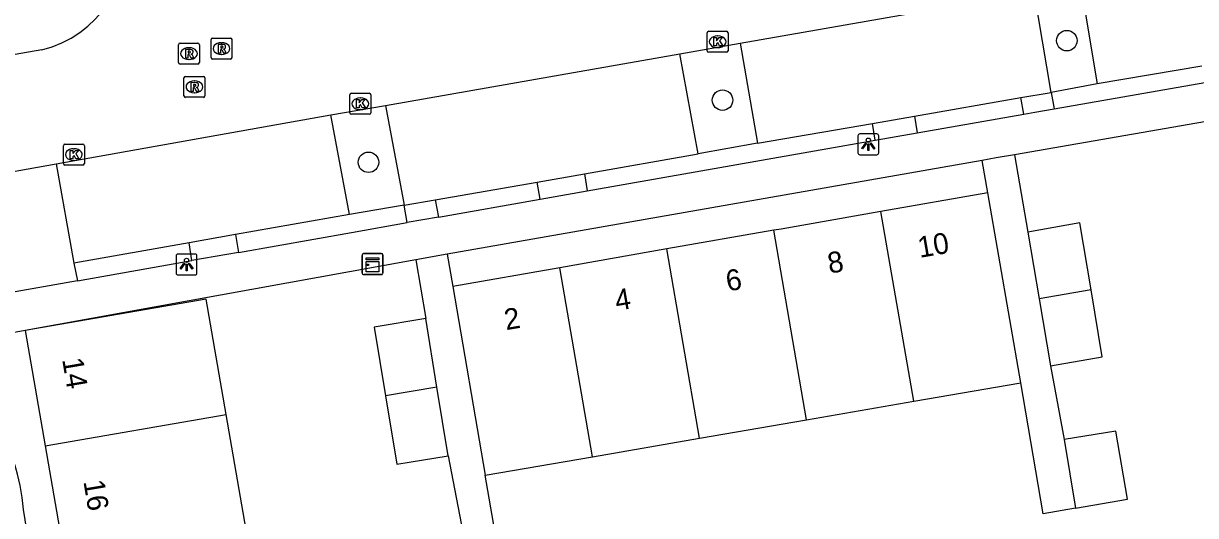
# Model space of a CAD drawing. Extents: x 160158 to 160921, y 381517 to 382041.
# Drawn here: x 160426.6 to 160482.6, y 381562.6 to 381586.1 of the extents above; entities that cross this region are included whole.
import ezdxf

# ---------------------------------------------------------------- set-up
doc = ezdxf.new("R2010")
doc.units = 0
for name, color, linetype in [('IMGEO_Boom', 7, 'Continuous'), ('IMGEO_Haag', 7, 'Continuous'), ('IMGEO_Kast', 7, 'Continuous'), ('IMGEO_Kolk', 7, 'Continuous'), ('IMGEO_Lichtpunt', 7, 'Continuous'), ('IMGEO_Pand', 7, 'Continuous'), ('IMGEO_Pand_nummerreeks', 7, 'Continuous'), ('IMGEO_Parkeervlak_open', 7, 'Continuous'), ('IMGEO_Rijbaan_lokaal_open', 7, 'Continuous'), ('IMGEO_Rioolput', 7, 'Continuous'), ('IMGEO_Voetpad_open', 7, 'Continuous')]:
    doc.layers.add(name, color=color, linetype=linetype)

msp = doc.modelspace()

# ---------------------------------------------------------------- linework, layer by layer
at = {"layer": 'IMGEO_Boom'}
for centre in [(160476.481, 381585.284), (160460.03, 381582.444), (160443.111, 381579.477)]:
    msp.add_circle(centre, 0.489, dxfattribs=at)
at = {"layer": 'IMGEO_Haag'}
for points in [[(160477.934, 381583.215), (160475.736, 381582.816)], [(160461.706, 381580.383), (160458.87, 381579.878)], [(160444.822, 381577.426), (160442.204, 381576.98)], [(160429.039, 381574.668), (160429.203, 381573.814)]]:
    msp.add_lwpolyline(points, dxfattribs=at)
at = {"layer": 'IMGEO_Kast'}
for p, q in [((160442.805, 381574.193), (160442.805, 381575.034)), ((160442.805, 381575.034), (160442.805, 381574.193)), ((160442.88, 381575.118), (160443.721, 381575.118)), ((160443.721, 381575.118), (160442.88, 381575.118)), ((160443.805, 381575.043), (160443.805, 381574.202)), ((160443.805, 381574.202), (160443.805, 381575.043)), ((160443.73, 381574.118), (160442.889, 381574.118)), ((160442.889, 381574.118), (160443.73, 381574.118))]:
    msp.add_line(p, q, dxfattribs=at)
for points in [[(160443, 381574.908), (160443.6, 381574.908), (160443.6, 381574.823), (160443, 381574.823), (160443, 381574.908)], [(160443, 381574.733), (160443.6, 381574.733), (160443.6, 381574.244), (160443, 381574.244), (160443, 381574.733)]]:
    msp.add_lwpolyline(points, dxfattribs=at)
msp.add_circle((160443.084, 381574.582), 0.0377, dxfattribs=at)
for centre, start, end in [((160442.883, 381575.04), 92.4484, 184.2845), ((160442.883, 381575.04), 92.4484, 184.2845), ((160443.727, 381575.04), 2.4484, 94.2845), ((160443.727, 381575.04), 2.4484, 94.2845), ((160442.883, 381574.196), 182.4484, 274.2845), ((160442.883, 381574.196), 182.4484, 274.2845), ((160443.727, 381574.196), 272.4484, 4.2845), ((160443.727, 381574.196), 272.4484, 4.2845)]:
    msp.add_arc(centre, 0.0779, start, end, dxfattribs=at)
at = {"layer": 'IMGEO_Kolk'}
for p, q in [((160459.296, 381584.805), (160459.296, 381585.657)), ((160459.371, 381585.731), (160460.223, 381585.731)), ((160460.297, 381585.657), (160460.297, 381584.805)), ((160459.784, 381585.511), (160459.809, 381585.511)), ((160460.223, 381584.731), (160459.371, 381584.731)), ((160459.807, 381584.951), (160459.782, 381584.951)), ((160442.298, 381582.77), (160443.15, 381582.77)), ((160442.223, 381581.844), (160442.223, 381582.696)), ((160442.711, 381582.55), (160442.736, 381582.55)), ((160443.224, 381582.696), (160443.224, 381581.844)), ((160443.15, 381581.77), (160442.298, 381581.77)), ((160442.734, 381581.99), (160442.709, 381581.99)), ((160428.536, 381579.418), (160428.536, 381580.27)), ((160428.611, 381580.344), (160429.463, 381580.344)), ((160429.024, 381580.124), (160429.049, 381580.124)), ((160429.537, 381580.27), (160429.537, 381579.418)), ((160429.047, 381579.564), (160429.022, 381579.564)), ((160429.463, 381579.344), (160428.611, 381579.344))]:
    msp.add_line(p, q, dxfattribs=at)
for points in [[(160459.296, 381584.805), (160459.296, 381585.657)], [(160459.371, 381585.731), (160460.223, 381585.731)], [(160460.297, 381585.657), (160460.297, 381584.805)], [(160459.617, 381585.431), (160459.74, 381585.431), (160459.74, 381585.28), (160459.87, 381585.431), (160460.034, 381585.431), (160459.888, 381585.28), (160460.041, 381585.031), (160459.889, 381585.031), (160459.804, 381585.195), (160459.74, 381585.128), (160459.74, 381585.031), (160459.617, 381585.031), (160459.617, 381585.431)], [(160460.223, 381584.731), (160459.371, 381584.731)], [(160442.298, 381582.77), (160443.15, 381582.77)], [(160442.223, 381581.844), (160442.223, 381582.696)], [(160442.544, 381582.47), (160442.667, 381582.47), (160442.667, 381582.319), (160442.797, 381582.47), (160442.961, 381582.47), (160442.815, 381582.319), (160442.968, 381582.07), (160442.816, 381582.07), (160442.731, 381582.234), (160442.667, 381582.167), (160442.667, 381582.07), (160442.544, 381582.07), (160442.544, 381582.47)], [(160443.224, 381582.696), (160443.224, 381581.844)], [(160443.15, 381581.77), (160442.298, 381581.77)], [(160428.536, 381579.418), (160428.536, 381580.27)], [(160428.611, 381580.344), (160429.463, 381580.344)], [(160428.857, 381580.044), (160428.98, 381580.044), (160428.98, 381579.893), (160429.11, 381580.044), (160429.274, 381580.044), (160429.128, 381579.893), (160429.281, 381579.644), (160429.129, 381579.644), (160429.044, 381579.808), (160428.98, 381579.741), (160428.98, 381579.644), (160428.857, 381579.644), (160428.857, 381580.044)], [(160429.537, 381580.27), (160429.537, 381579.418)], [(160429.463, 381579.344), (160428.611, 381579.344)]]:
    msp.add_lwpolyline(points, dxfattribs=at)
for centre, start, end in [((160459.373, 381585.655), 91.552, 178.448), ((160459.373, 381585.655), 91.552, 178.448), ((160460.221, 381585.655), 1.552, 88.448), ((160460.221, 381585.655), 1.552, 88.448), ((160459.373, 381584.807), 181.552, 268.448), ((160459.373, 381584.807), 181.552, 268.448), ((160460.221, 381584.807), 271.552, 358.448), ((160460.221, 381584.807), 271.552, 358.448), ((160442.3, 381582.694), 91.552, 178.448), ((160442.3, 381582.694), 91.552, 178.448), ((160443.148, 381582.694), 1.552, 88.448), ((160443.148, 381582.694), 1.552, 88.448), ((160442.3, 381581.846), 181.552, 268.448), ((160442.3, 381581.846), 181.552, 268.448), ((160443.148, 381581.846), 271.552, 358.448), ((160443.148, 381581.846), 271.552, 358.448), ((160428.613, 381580.268), 91.552, 178.448), ((160428.613, 381580.268), 91.552, 178.448), ((160429.461, 381580.268), 1.552, 88.448), ((160429.461, 381580.268), 1.552, 88.448), ((160428.613, 381579.42), 181.552, 268.448), ((160428.613, 381579.42), 181.552, 268.448), ((160429.461, 381579.42), 271.552, 358.448), ((160429.461, 381579.42), 271.552, 358.448)]:
    msp.add_arc(centre, 0.0765, start, end, dxfattribs=at)
for centre, major_axis, ratio, start_param, end_param in [((160459.783, 381585.231), (-0.387, 0.002), 0.722429, 4.712389, 7.853982), ((160459.808, 381585.231), (-0.39, 0.002), 0.717154, 1.570796, 4.712389), ((160442.71, 381582.27), (-0.387, 0.002), 0.722429, 4.712389, 7.853982), ((160442.735, 381582.27), (-0.39, 0.002), 0.717154, 1.570796, 4.712389), ((160429.023, 381579.844), (-0.387, 0.002), 0.722429, 4.712389, 7.853982), ((160429.048, 381579.844), (-0.39, 0.002), 0.717154, 1.570796, 4.712389)]:
    msp.add_ellipse(centre, major_axis=major_axis, ratio=ratio, start_param=start_param, end_param=end_param, dxfattribs=at)
at = {"layer": 'IMGEO_Lichtpunt'}
for p, q in [((160466.497, 381580.738), (160466.497, 381579.931)), ((160466.497, 381580.738), (160466.497, 381579.931)), ((160467.399, 381580.833), (160466.591, 381580.833)), ((160467.399, 381580.833), (160466.591, 381580.833)), ((160467.493, 381579.931), (160467.493, 381580.738)), ((160467.493, 381579.931), (160467.493, 381580.738)), ((160466.591, 381579.837), (160467.399, 381579.837)), ((160466.591, 381579.837), (160467.399, 381579.837)), ((160433.922, 381575.001), (160433.922, 381574.194)), ((160433.922, 381575.001), (160433.922, 381574.194)), ((160434.824, 381575.096), (160434.016, 381575.096)), ((160434.824, 381575.096), (160434.016, 381575.096)), ((160434.918, 381574.194), (160434.918, 381575.001)), ((160434.918, 381574.194), (160434.918, 381575.001)), ((160434.016, 381574.1), (160434.824, 381574.1)), ((160434.016, 381574.1), (160434.824, 381574.1))]:
    msp.add_line(p, q, dxfattribs=at)
for points in [[(160466.871, 381580.402), (160466.91, 381580.374), (160466.722, 381580.112), (160466.684, 381580.139), (160466.871, 381580.402)], [(160466.973, 381580.354), (160467.02, 381580.354), (160467.02, 381580.032), (160466.973, 381580.032), (160466.973, 381580.354)], [(160467.083, 381580.374), (160467.121, 381580.401), (160467.308, 381580.139), (160467.269, 381580.111), (160467.083, 381580.374)], [(160434.296, 381574.665), (160434.335, 381574.637), (160434.147, 381574.375), (160434.109, 381574.402), (160434.296, 381574.665)], [(160434.398, 381574.617), (160434.445, 381574.617), (160434.445, 381574.295), (160434.398, 381574.295), (160434.398, 381574.617)], [(160434.508, 381574.637), (160434.546, 381574.664), (160434.733, 381574.402), (160434.694, 381574.374), (160434.508, 381574.637)]]:
    msp.add_lwpolyline(points, dxfattribs=at)
for centre in [(160466.996, 381580.536), (160434.421, 381574.799)]:
    msp.add_circle(centre, 0.0994, dxfattribs=at)
for centre, start, end in [((160466.591, 381580.738), 90, 180), ((160466.591, 381580.738), 90, 180), ((160467.399, 381580.738), 0, 90), ((160467.399, 381580.738), 0, 90), ((160466.591, 381579.931), 180, 270), ((160466.591, 381579.931), 180, 270), ((160467.399, 381579.931), 270, 0), ((160467.399, 381579.931), 270, 360), ((160434.016, 381575.001), 90, 180), ((160434.016, 381575.001), 90, 180), ((160434.824, 381575.001), 0, 90), ((160434.824, 381575.001), 0, 90), ((160434.016, 381574.194), 180, 270), ((160434.016, 381574.194), 180, 270), ((160434.824, 381574.194), 270, 0), ((160434.824, 381574.194), 270, 360)]:
    msp.add_arc(centre, 0.0946, start, end, dxfattribs=at)
at = {"layer": 'IMGEO_Pand'}
for points in [[(160472.714, 381578.016), (160467.601, 381577.123)], [(160474.281, 381568.948), (160472.714, 381578.016)], [(160467.601, 381577.123), (160462.828, 381576.289), (160462.488, 381576.23)], [(160469.164, 381568.066), (160467.601, 381577.123)], [(160477.637, 381573.391), (160477.097, 381576.593), (160474.621, 381576.147)], [(160462.488, 381576.23), (160457.375, 381575.337)], [(160464.047, 381567.185), (160462.488, 381576.23)], [(160474.621, 381576.147), (160475.162, 381572.954)], [(160457.375, 381575.337), (160452.262, 381574.444)], [(160458.929, 381566.303), (160457.375, 381575.337)], [(160452.262, 381574.444), (160447.149, 381573.551)], [(160453.812, 381565.422), (160452.262, 381574.444)], [(160447.149, 381573.551), (160448.695, 381564.54)], [(160477.637, 381573.391), (160475.162, 381572.954)], [(160475.702, 381569.761), (160478.177, 381570.188), (160477.637, 381573.391)], [(160436.314, 381567.442), (160435.356, 381572.949), (160426.71, 381571.443)], [(160475.162, 381572.954), (160475.702, 381569.761)], [(160445.847, 381572.014), (160443.389, 381571.602), (160443.928, 381568.33)], [(160446.387, 381568.739), (160445.847, 381572.014)], [(160426.71, 381571.443), (160427.667, 381565.936)], [(160469.164, 381568.066), (160474.281, 381568.948)], [(160446.387, 381568.739), (160443.928, 381568.33)], [(160443.928, 381568.33), (160444.468, 381565.058), (160446.927, 381565.464)], [(160446.927, 381565.464), (160446.387, 381568.739)], [(160464.047, 381567.185), (160469.164, 381568.066)], [(160427.667, 381565.936), (160436.314, 381567.442)], [(160437.271, 381561.934), (160436.314, 381567.442)], [(160458.929, 381566.303), (160464.047, 381567.185)], [(160476.902, 381562.957), (160479.376, 381563.387), (160478.83, 381566.646), (160476.347, 381566.239)], [(160453.812, 381565.422), (160458.929, 381566.303)], [(160476.347, 381566.239), (160476.902, 381562.957)], [(160427.667, 381565.936), (160428.625, 381560.43)], [(160448.695, 381564.54), (160453.812, 381565.422)]]:
    msp.add_lwpolyline(points, dxfattribs=at)
at = {"layer": 'IMGEO_Parkeervlak_open'}
for points in [[(160477.14, 381588.004), (160477.934, 381583.215)], [(160475.736, 381582.816), (160474.925, 381587.623)], [(160460.872, 381585.165), (160461.706, 381580.383)], [(160458.87, 381579.878), (160457.992, 381584.659)], [(160482.925, 381584.072), (160477.934, 381583.215)], [(160469.197, 381581.682), (160474.29, 381582.565)], [(160442.204, 381576.98), (160441.322, 381581.744)], [(160443.92, 381582.187), (160444.822, 381577.426)], [(160461.706, 381580.383), (160467.188, 381581.334)], [(160428.192, 381579.402), (160429.039, 381574.668)], [(160453.429, 381578.928), (160458.87, 381579.878)], [(160446.299, 381577.684), (160451.17, 381578.534)], [(160442.204, 381576.98), (160436.753, 381576.023)], [(160434.543, 381575.635), (160429.039, 381574.668)]]:
    msp.add_lwpolyline(points, dxfattribs=at)
at = {"layer": 'IMGEO_Rijbaan_lokaal_open'}
for points in [[(160460.872, 381585.165), (160474.925, 381587.623)], [(160457.992, 381584.659), (160460.872, 381585.165)], [(160427.508, 381584.838), (160422.1, 381583.909)], [(160443.92, 381582.187), (160457.992, 381584.659)], [(160428.192, 381579.402), (160441.322, 381581.744)], [(160441.322, 381581.744), (160443.92, 381582.187)], [(160424.425, 381578.731), (160428.192, 381579.402)]]:
    msp.add_lwpolyline(points, dxfattribs=at)
msp.add_arc((160426.158, 381590.124), 5.456, 284.3246, 7.1148, dxfattribs=at)
at = {"layer": 'IMGEO_Rioolput'}
for p, q in [((160434.036, 381584.239), (160434.036, 381585.091)), ((160434.111, 381585.165), (160434.963, 381585.165)), ((160435.037, 381585.091), (160435.037, 381584.239)), ((160435.591, 381584.481), (160435.591, 381585.333)), ((160435.666, 381585.407), (160436.518, 381585.407)), ((160436.079, 381585.187), (160436.104, 381585.187)), ((160436.592, 381585.333), (160436.592, 381584.481)), ((160434.524, 381584.945), (160434.549, 381584.945)), ((160436.102, 381584.627), (160436.077, 381584.627)), ((160434.963, 381584.165), (160434.111, 381584.165)), ((160434.547, 381584.385), (160434.522, 381584.385)), ((160436.518, 381584.407), (160435.666, 381584.407)), ((160434.296, 381582.652), (160434.296, 381583.504)), ((160434.371, 381583.578), (160435.223, 381583.578)), ((160434.784, 381583.358), (160434.809, 381583.358)), ((160435.297, 381583.504), (160435.297, 381582.652)), ((160434.807, 381582.798), (160434.782, 381582.798)), ((160435.223, 381582.578), (160434.371, 381582.578))]:
    msp.add_line(p, q, dxfattribs=at)
for points in [[(160434.036, 381584.239), (160434.036, 381585.091)], [(160434.111, 381585.165), (160434.963, 381585.165)], [(160435.037, 381585.091), (160435.037, 381584.239)], [(160435.591, 381584.481), (160435.591, 381585.333)], [(160435.666, 381585.407), (160436.518, 381585.407)], [(160436.18, 381585.105), (160435.928, 381585.107), (160435.928, 381584.707)], [(160436.106, 381585.026), (160436.052, 381585.026), (160436.052, 381584.945)], [(160436.592, 381585.333), (160436.592, 381584.481)], [(160434.625, 381584.863), (160434.373, 381584.865), (160434.373, 381584.465)], [(160434.373, 381584.465), (160434.497, 381584.465), (160434.497, 381584.627), (160434.508, 381584.627)], [(160434.551, 381584.784), (160434.497, 381584.784), (160434.497, 381584.703)], [(160434.497, 381584.703), (160434.549, 381584.703)], [(160434.555, 381584.598), (160434.626, 381584.465), (160434.766, 381584.465), (160434.701, 381584.591)], [(160435.928, 381584.707), (160436.052, 381584.707), (160436.052, 381584.869), (160436.063, 381584.869)], [(160436.052, 381584.945), (160436.104, 381584.945)], [(160436.11, 381584.84), (160436.181, 381584.707), (160436.321, 381584.707), (160436.256, 381584.833)], [(160434.963, 381584.165), (160434.111, 381584.165)], [(160436.518, 381584.407), (160435.666, 381584.407)], [(160434.296, 381582.652), (160434.296, 381583.504)], [(160434.371, 381583.578), (160435.223, 381583.578)], [(160435.297, 381583.504), (160435.297, 381582.652)], [(160434.885, 381583.276), (160434.633, 381583.278), (160434.633, 381582.878)], [(160434.633, 381582.878), (160434.757, 381582.878), (160434.757, 381583.04), (160434.768, 381583.04)], [(160434.811, 381583.197), (160434.757, 381583.197), (160434.757, 381583.116)], [(160434.757, 381583.116), (160434.809, 381583.116)], [(160434.815, 381583.011), (160434.886, 381582.878), (160435.026, 381582.878), (160434.961, 381583.004)], [(160435.223, 381582.578), (160434.371, 381582.578)]]:
    msp.add_lwpolyline(points, dxfattribs=at)
for centre, radius, start, end in [((160434.113, 381585.089), 0.0765, 91.552, 178.448), ((160434.113, 381585.089), 0.0765, 91.552, 178.448), ((160434.961, 381585.089), 0.0765, 1.552, 88.448), ((160434.961, 381585.089), 0.0765, 1.552, 88.448), ((160435.668, 381585.331), 0.0765, 91.552, 178.448), ((160435.668, 381585.331), 0.0765, 91.552, 178.448), ((160436.112, 381584.93), 0.0964, 77.0061, 93.1865), ((160436.126, 381584.987), 0.0378, 276.6634, 79.6772), ((160436.179, 381584.995), 0.109, 350.3612, 89.416), ((160436.516, 381585.331), 0.0765, 1.552, 88.448), ((160436.516, 381585.331), 0.0765, 1.552, 88.448), ((160434.507, 381584.574), 0.0533, 26.0293, 88.6989), ((160434.533, 381584.892), 0.19, 274.7715, 282.9687), ((160434.557, 381584.688), 0.0964, 77.0061, 93.1865), ((160434.571, 381584.745), 0.0378, 276.6634, 79.6772), ((160434.624, 381584.753), 0.109, 350.3612, 89.416), ((160434.622, 381584.753), 0.112, 277.5842, 350.9817), ((160434.606, 381584.538), 0.108, 29.5134, 73.7905), ((160435.668, 381584.483), 0.0765, 181.552, 268.448), ((160435.668, 381584.483), 0.0765, 181.552, 268.448), ((160436.062, 381584.816), 0.0533, 26.0293, 88.6989), ((160436.088, 381585.134), 0.19, 274.7715, 282.9687), ((160436.177, 381584.995), 0.112, 277.5842, 350.9817), ((160436.161, 381584.78), 0.108, 29.5134, 73.7905), ((160436.516, 381584.483), 0.0765, 271.552, 358.448), ((160436.516, 381584.483), 0.0765, 271.552, 358.448), ((160434.113, 381584.241), 0.0765, 181.552, 268.448), ((160434.113, 381584.241), 0.0765, 181.552, 268.448), ((160434.961, 381584.241), 0.0765, 271.552, 358.448), ((160434.961, 381584.241), 0.0765, 271.552, 358.448), ((160434.373, 381583.502), 0.0765, 91.552, 178.448), ((160434.373, 381583.502), 0.0765, 91.552, 178.448), ((160435.221, 381583.502), 0.0765, 1.552, 88.448), ((160435.221, 381583.502), 0.0765, 1.552, 88.448), ((160434.767, 381582.987), 0.0533, 26.0293, 88.6989), ((160434.793, 381583.305), 0.19, 274.7715, 282.9687), ((160434.817, 381583.101), 0.0964, 77.0061, 93.1865), ((160434.831, 381583.158), 0.0378, 276.6634, 79.6772), ((160434.884, 381583.166), 0.109, 350.3612, 89.416), ((160434.882, 381583.166), 0.112, 277.5842, 350.9817), ((160434.866, 381582.951), 0.108, 29.5134, 73.7905), ((160434.373, 381582.654), 0.0765, 181.552, 268.448), ((160434.373, 381582.654), 0.0765, 181.552, 268.448), ((160435.221, 381582.654), 0.0765, 271.552, 358.448), ((160435.221, 381582.654), 0.0765, 271.552, 358.448)]:
    msp.add_arc(centre, radius, start, end, dxfattribs=at)
for centre, major_axis, ratio, start_param, end_param in [((160436.078, 381584.907), (-0.387, 0.002), 0.722429, 4.712389, 7.853982), ((160436.103, 381584.907), (-0.39, 0.002), 0.717154, 1.570796, 4.712389), ((160434.523, 381584.665), (-0.387, 0.002), 0.722429, 4.712389, 7.853982), ((160434.548, 381584.665), (-0.39, 0.002), 0.717154, 1.570796, 4.712389), ((160434.783, 381583.078), (-0.387, 0.002), 0.722429, 4.712389, 7.853982), ((160434.808, 381583.078), (-0.39, 0.002), 0.717154, 1.570796, 4.712389)]:
    msp.add_ellipse(centre, major_axis=major_axis, ratio=ratio, start_param=start_param, end_param=end_param, dxfattribs=at)
at = {"layer": 'IMGEO_Voetpad_open'}
for points in [[(160503.713, 381545.771), (160497.086, 381583.845), (160473.981, 381579.836)], [(160474.29, 381582.565), (160475.736, 381582.816)], [(160475.736, 381582.816), (160475.88, 381582.035)], [(160475.88, 381582.035), (160483.08, 381583.281)], [(160474.422, 381581.781), (160474.29, 381582.565)], [(160467.188, 381581.334), (160469.197, 381581.682)], [(160469.197, 381581.682), (160469.325, 381580.884)], [(160469.325, 381580.884), (160474.422, 381581.781)], [(160474.422, 381581.781), (160474.951, 381581.874), (160475.88, 381582.035)], [(160467.315, 381580.53), (160467.188, 381581.334)], [(160453.562, 381578.108), (160467.315, 381580.53)], [(160467.315, 381580.53), (160469.325, 381580.884)], [(160472.442, 381579.568), (160446.879, 381575.09)], [(160473.981, 381579.836), (160473.099, 381579.683), (160472.442, 381579.568)], [(160472.714, 381578.016), (160472.442, 381579.568)], [(160473.981, 381579.836), (160474.621, 381576.147)], [(160451.17, 381578.534), (160453.429, 381578.928)], [(160453.429, 381578.928), (160453.562, 381578.108)], [(160451.316, 381577.712), (160451.17, 381578.534)], [(160446.452, 381576.856), (160451.316, 381577.712)], [(160451.316, 381577.712), (160453.562, 381578.108)], [(160444.822, 381577.426), (160446.299, 381577.684)], [(160444.965, 381576.595), (160444.822, 381577.426)], [(160446.299, 381577.684), (160446.452, 381576.856)], [(160436.9, 381575.172), (160442.304, 381576.126), (160444.965, 381576.595)], [(160446.452, 381576.856), (160444.965, 381576.595)], [(160436.753, 381576.023), (160434.543, 381575.635)], [(160434.676, 381574.78), (160434.543, 381575.635)], [(160436.753, 381576.023), (160436.9, 381575.172)], [(160436.9, 381575.172), (160434.676, 381574.78)], [(160446.879, 381575.09), (160445.371, 381574.826)], [(160446.879, 381575.09), (160447.149, 381573.551)], [(160445.371, 381574.826), (160426.71, 381571.443)], [(160429.203, 381573.814), (160434.676, 381574.78)], [(160445.371, 381574.826), (160445.847, 381572.014)], [(160429.203, 381573.814), (160420.44, 381572.267)], [(160426.71, 381571.443), (160422.355, 381570.648)], [(160475.702, 381569.761), (160476.347, 381566.239)], [(160476.902, 381562.957), (160475.354, 381562.692), (160474.281, 381568.948)], [(160446.927, 381565.464), (160447.703, 381561.4)], [(160452.482, 381555.001), (160450.412, 381554.635), (160448.695, 381564.54)], [(160431.85, 381530.539), (160426.627, 381562.902)]]:
    msp.add_lwpolyline(points, dxfattribs=at)
msp.add_arc((160415.661, 381561.905), 11.011, 5.1939, 52.5605, dxfattribs=at)

# ---------------------------------------------------------------- texts
at = {"layer": 'IMGEO_Pand_nummerreeks'}
for s, rotation, p in [('10', 9.7116, (160469.448, 381574.911)), ('8', 9.7116, (160465.14, 381574.157)), ('6', 9.7116, (160460.279, 381573.308)), ('4', 9.7116, (160454.976, 381572.381)), ('2', 9.7116, (160449.688, 381571.458)), ('14', 279.6656, (160428.474, 381570.068)), ('16', 279.6656, (160429.488, 381564.239))]:
    msp.add_text(s, height=1, rotation=rotation, dxfattribs=at).set_placement(p)

doc.saveas('drawing.dxf')
